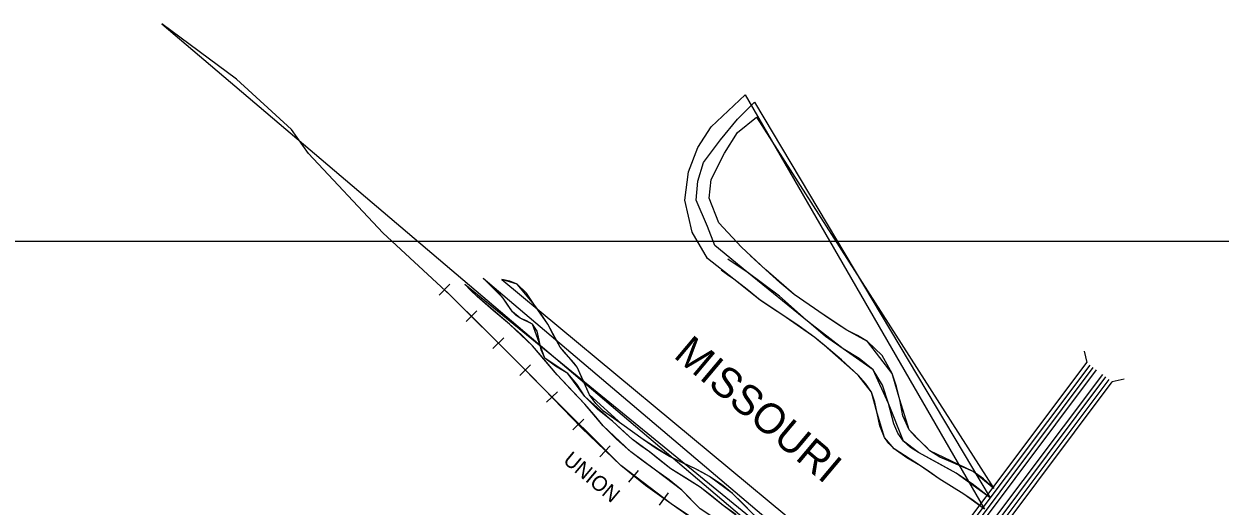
# Model space of a CAD drawing. Extents: x 5.01 to 9.58, y 0.27 to 3.39.
# Drawn here: x 8.037 to 8.957, y 3.015 to 3.387 of the extents above; entities that cross this region are included whole.
import ezdxf

# ---------------------------------------------------------------- set-up
doc = ezdxf.new("R2010")
doc.units = 0
for name, color, linetype in [('MO_001_NOSHOW', 7, 'Continuous'), ('MO_001_VIEW_99', 7, 'Continuous'), ('MO_001_VIEW_PV', 7, 'Continuous')]:
    doc.layers.add(name, color=color, linetype=linetype)

msp = doc.modelspace()

# ---------------------------------------------------------------- linework, layer by layer
at = {"layer": 'MO_001_NOSHOW'}
for points in [[(8.70157, 2.9117), (8.65869, 2.93369), (8.62541, 2.95034), (8.59027, 2.97807), (8.5348, 3.0169), (8.49598, 3.04649), (8.4368, 3.10566), (8.41461, 3.12785), (8.36468, 3.17778), (8.31291, 3.22585), (8.25559, 3.28687), (8.24264, 3.30537), (8.20011, 3.3442), (8.14278, 3.38672)], [(8.776, 3.01295), (8.76004, 3.02456), (8.74117, 3.03617), (8.72666, 3.04634), (8.70635, 3.05939), (8.69909, 3.0681), (8.69329, 3.08696), (8.68893, 3.10292), (8.67877, 3.11599), (8.65266, 3.1392), (8.6454, 3.14501), (8.62074, 3.16242), (8.60331, 3.17402), (8.583, 3.18999), (8.56269, 3.20595), (8.55108, 3.22627), (8.54528, 3.25093), (8.54817, 3.27271), (8.55544, 3.29157), (8.56559, 3.30753), (8.59171, 3.3322)], [(8.78035, 3.02166), (8.75423, 3.04053), (8.72521, 3.05649), (8.7136, 3.0652), (8.702, 3.09421), (8.69038, 3.12034), (8.66716, 3.1363), (8.64105, 3.15661), (8.59316, 3.1958), (8.56849, 3.21611), (8.56269, 3.23062), (8.55399, 3.25093), (8.55544, 3.26545), (8.55979, 3.27996), (8.57285, 3.29737), (8.5859, 3.31333), (8.59896, 3.32639)], [(8.78326, 3.02891), (8.7673, 3.04198), (8.73392, 3.05794), (8.72811, 3.06375), (8.71796, 3.0739), (8.7107, 3.09712), (8.7049, 3.11744), (8.68602, 3.1421), (8.67007, 3.15081), (8.65266, 3.16242), (8.62944, 3.17838), (8.60767, 3.19725), (8.58881, 3.21466), (8.5714, 3.23352), (8.56414, 3.25238), (8.56559, 3.2669), (8.57575, 3.28721), (8.5859, 3.30317), (8.60041, 3.31478)], [(8.70095, 2.92061), (8.68276, 2.92791), (8.6638, 2.94214), (8.64011, 2.95398), (8.62826, 2.96465), (8.61286, 2.97412), (8.5939, 2.98716), (8.57849, 2.99901), (8.55717, 3.01322), (8.54295, 3.02744), (8.52281, 3.04284), (8.50385, 3.05706), (8.48253, 3.07719), (8.46831, 3.09379), (8.44699, 3.11629), (8.42803, 3.13881), (8.41027, 3.15539), (8.38538, 3.17672), (8.37591, 3.1862)], [(8.70383, 2.92445), (8.69341, 2.92911), (8.6792, 2.93384), (8.66143, 2.95043), (8.64722, 2.95991), (8.63299, 2.9682), (8.62233, 2.97768), (8.60812, 2.98716), (8.5939, 3.00137), (8.57494, 3.01559), (8.55717, 3.0298), (8.53466, 3.04403), (8.51808, 3.05706), (8.50505, 3.06654), (8.48964, 3.08075), (8.46831, 3.09971), (8.45528, 3.11748), (8.43751, 3.12933), (8.42803, 3.15539), (8.41856, 3.16014), (8.41263, 3.16487), (8.40552, 3.17553), (8.39605, 3.18501), (8.39012, 3.19093)], [(8.71146, 2.93463), (8.69223, 2.93977), (8.67565, 2.94806), (8.66262, 2.95754), (8.6484, 2.96701), (8.63891, 2.9765), (8.6247, 2.98597), (8.6093, 2.99901), (8.59745, 3.00966), (8.58205, 3.02507), (8.56428, 3.03811), (8.55362, 3.04403), (8.53348, 3.0535), (8.51334, 3.06654), (8.49674, 3.07839), (8.47187, 3.1009), (8.46239, 3.12222), (8.45766, 3.12814), (8.44935, 3.13762), (8.43988, 3.15539), (8.42921, 3.17079), (8.41619, 3.1862), (8.40434, 3.18975)]]:
    msp.add_lwpolyline(points, close=True, dxfattribs=at)
at = {"layer": 'MO_001_VIEW_99'}
msp.add_line((5.01404, 3.2194), (9.57964, 3.2194), dxfattribs=at)
at = {"layer": 'MO_001_VIEW_PV'}
for p, q in [((8.35635, 3.17766), (8.36446, 3.1862)), ((8.37708, 3.15737), (8.38533, 3.16562)), ((8.39766, 3.13664), (8.40591, 3.14475)), ((8.85262, 3.13461), (8.8548, 3.12577)), ((8.41839, 3.11592), (8.42664, 3.12417)), ((8.68478, 2.89908), (8.8548, 3.12577)), ((8.68724, 2.8972), (8.85726, 3.12389)), ((8.68971, 2.89531), (8.85972, 3.122)), ((8.69217, 2.89342), (8.86219, 3.12011)), ((8.69696, 2.88995), (8.86697, 3.11664)), ((8.69942, 2.88807), (8.86943, 3.11476)), ((8.70189, 2.88618), (8.87189, 3.11287)), ((8.8835, 3.11316), (8.87437, 3.11098)), ((8.43882, 3.09519), (8.44722, 3.1033)), ((8.70435, 2.8843), (8.87437, 3.11098)), ((8.45911, 3.07402), (8.46752, 3.08214)), ((8.47983, 3.05315), (8.48795, 3.06171)), ((8.50216, 3.03373), (8.50955, 3.04271)), ((8.52593, 3.0159), (8.53273, 3.02548))]:
    msp.add_line(p, q, dxfattribs=at)
for points in [[(8.7781, 3.02349), (8.76643, 3.03242), (8.75423, 3.04053), (8.73983, 3.04848), (8.72521, 3.05649), (8.719, 3.06048), (8.7136, 3.0652), (8.70929, 3.07139), (8.70625, 3.07851), (8.702, 3.09421), (8.69755, 3.10836), (8.69038, 3.12034), (8.67958, 3.12896), (8.66716, 3.1363), (8.65357, 3.14596), (8.64105, 3.15661), (8.61816, 3.17694), (8.59316, 3.1958), (8.58565, 3.20052), (8.57843, 3.20544)], [(8.78263, 3.02952), (8.77532, 3.03623), (8.7673, 3.04198), (8.75002, 3.04927), (8.74147, 3.05294), (8.73392, 3.05794), (8.73099, 3.06078), (8.72811, 3.06375), (8.72276, 3.06868), (8.71796, 3.0739), (8.71318, 3.08485), (8.7107, 3.09712), (8.70832, 3.10749), (8.7049, 3.11744), (8.69712, 3.13116), (8.68602, 3.1421), (8.67817, 3.14664), (8.67007, 3.15081), (8.66123, 3.15639), (8.65266, 3.16242), (8.64095, 3.17029), (8.62944, 3.17838), (8.61833, 3.18754), (8.60767, 3.19725), (8.60169, 3.20277), (8.59571, 3.20829)], [(8.77233, 3.01579), (8.76627, 3.02031), (8.76004, 3.02456), (8.75057, 3.03033), (8.74117, 3.03617), (8.73395, 3.0413), (8.72666, 3.04634), (8.71622, 3.05248), (8.70635, 3.05939), (8.70236, 3.06347), (8.69909, 3.0681), (8.69541, 3.07717), (8.69329, 3.08696), (8.69162, 3.09519), (8.68893, 3.10292), (8.68444, 3.10978), (8.67877, 3.11599), (8.66598, 3.128), (8.65266, 3.1392), (8.64905, 3.14212), (8.6454, 3.14501), (8.63326, 3.15398), (8.62074, 3.16242), (8.61193, 3.16811), (8.60331, 3.17402), (8.59319, 3.182), (8.583, 3.18999), (8.57809, 3.19347), (8.57316, 3.19694)], [(8.55717, 3.01322), (8.54999, 3.02022), (8.54295, 3.02744), (8.53319, 3.0355), (8.52281, 3.04284), (8.5132, 3.04979), (8.50385, 3.05706), (8.49281, 3.06672), (8.48253, 3.07719), (8.47542, 3.08548), (8.46831, 3.09379), (8.45763, 3.10503), (8.44699, 3.11629), (8.43758, 3.12761), (8.42803, 3.13881), (8.41941, 3.14736), (8.41027, 3.15539), (8.39767, 3.1659), (8.38538, 3.17672), (8.38058, 3.1814), (8.37591, 3.1862)], [(8.58462, 3.00871), (8.57494, 3.01559), (8.56609, 3.02277), (8.55717, 3.0298), (8.54593, 3.03692), (8.53466, 3.04403), (8.52633, 3.05048), (8.51808, 3.05706), (8.5115, 3.06173), (8.50505, 3.06654), (8.4973, 3.07357), (8.48964, 3.08075), (8.47842, 3.08974), (8.46831, 3.09971), (8.46229, 3.10908), (8.45528, 3.11748), (8.44579, 3.123), (8.43751, 3.12933), (8.4348, 3.13567), (8.43331, 3.14301), (8.43155, 3.15002), (8.42803, 3.15539), (8.42355, 3.15791), (8.41856, 3.16014), (8.41535, 3.16225), (8.41263, 3.16487), (8.409, 3.17013), (8.40552, 3.17553), (8.401, 3.18045), (8.39605, 3.18501), (8.39306, 3.18796), (8.39012, 3.19093)], [(8.59745, 3.00966), (8.58981, 3.01743), (8.58205, 3.02507), (8.57348, 3.032), (8.56428, 3.03811), (8.55901, 3.04118), (8.55362, 3.04403), (8.54351, 3.0487), (8.53348, 3.0535), (8.52319, 3.05969), (8.51334, 3.06654), (8.50511, 3.07246), (8.49674, 3.07839), (8.48283, 3.08848), (8.47672, 3.09425), (8.47187, 3.1009), (8.4673, 3.11162), (8.46239, 3.12222), (8.46016, 3.12527), (8.45766, 3.12814), (8.45334, 3.13278), (8.44935, 3.13762), (8.44442, 3.14637), (8.43988, 3.15539), (8.43475, 3.16314), (8.42921, 3.17079), (8.42336, 3.17934), (8.41619, 3.1862), (8.4105, 3.18862), (8.40434, 3.18975)], [(8.69633, 2.91444), (8.67762, 2.92427), (8.65869, 2.93369), (8.64174, 2.94155), (8.62541, 2.95034), (8.6075, 2.96364), (8.59027, 2.97807), (8.56292, 2.99803), (8.5348, 3.0169), (8.51496, 3.03116), (8.49598, 3.04649), (8.46581, 3.07545), (8.4368, 3.10566), (8.42574, 3.11678), (8.41461, 3.12785), (8.38973, 3.15292), (8.36468, 3.17778), (8.36252, 3.17986), (8.36035, 3.18194)]]:
    msp.add_lwpolyline(points, dxfattribs=at)

# ---------------------------------------------------------------- texts
for s, height, p in [('MISSOURI', 0.023189, (8.53587, 3.13034)), ('UNION', 0.011594, (8.45091, 3.0493))]:
    msp.add_text(s, height=height, rotation=320, dxfattribs=at).set_placement(p)

doc.saveas('drawing.dxf')
